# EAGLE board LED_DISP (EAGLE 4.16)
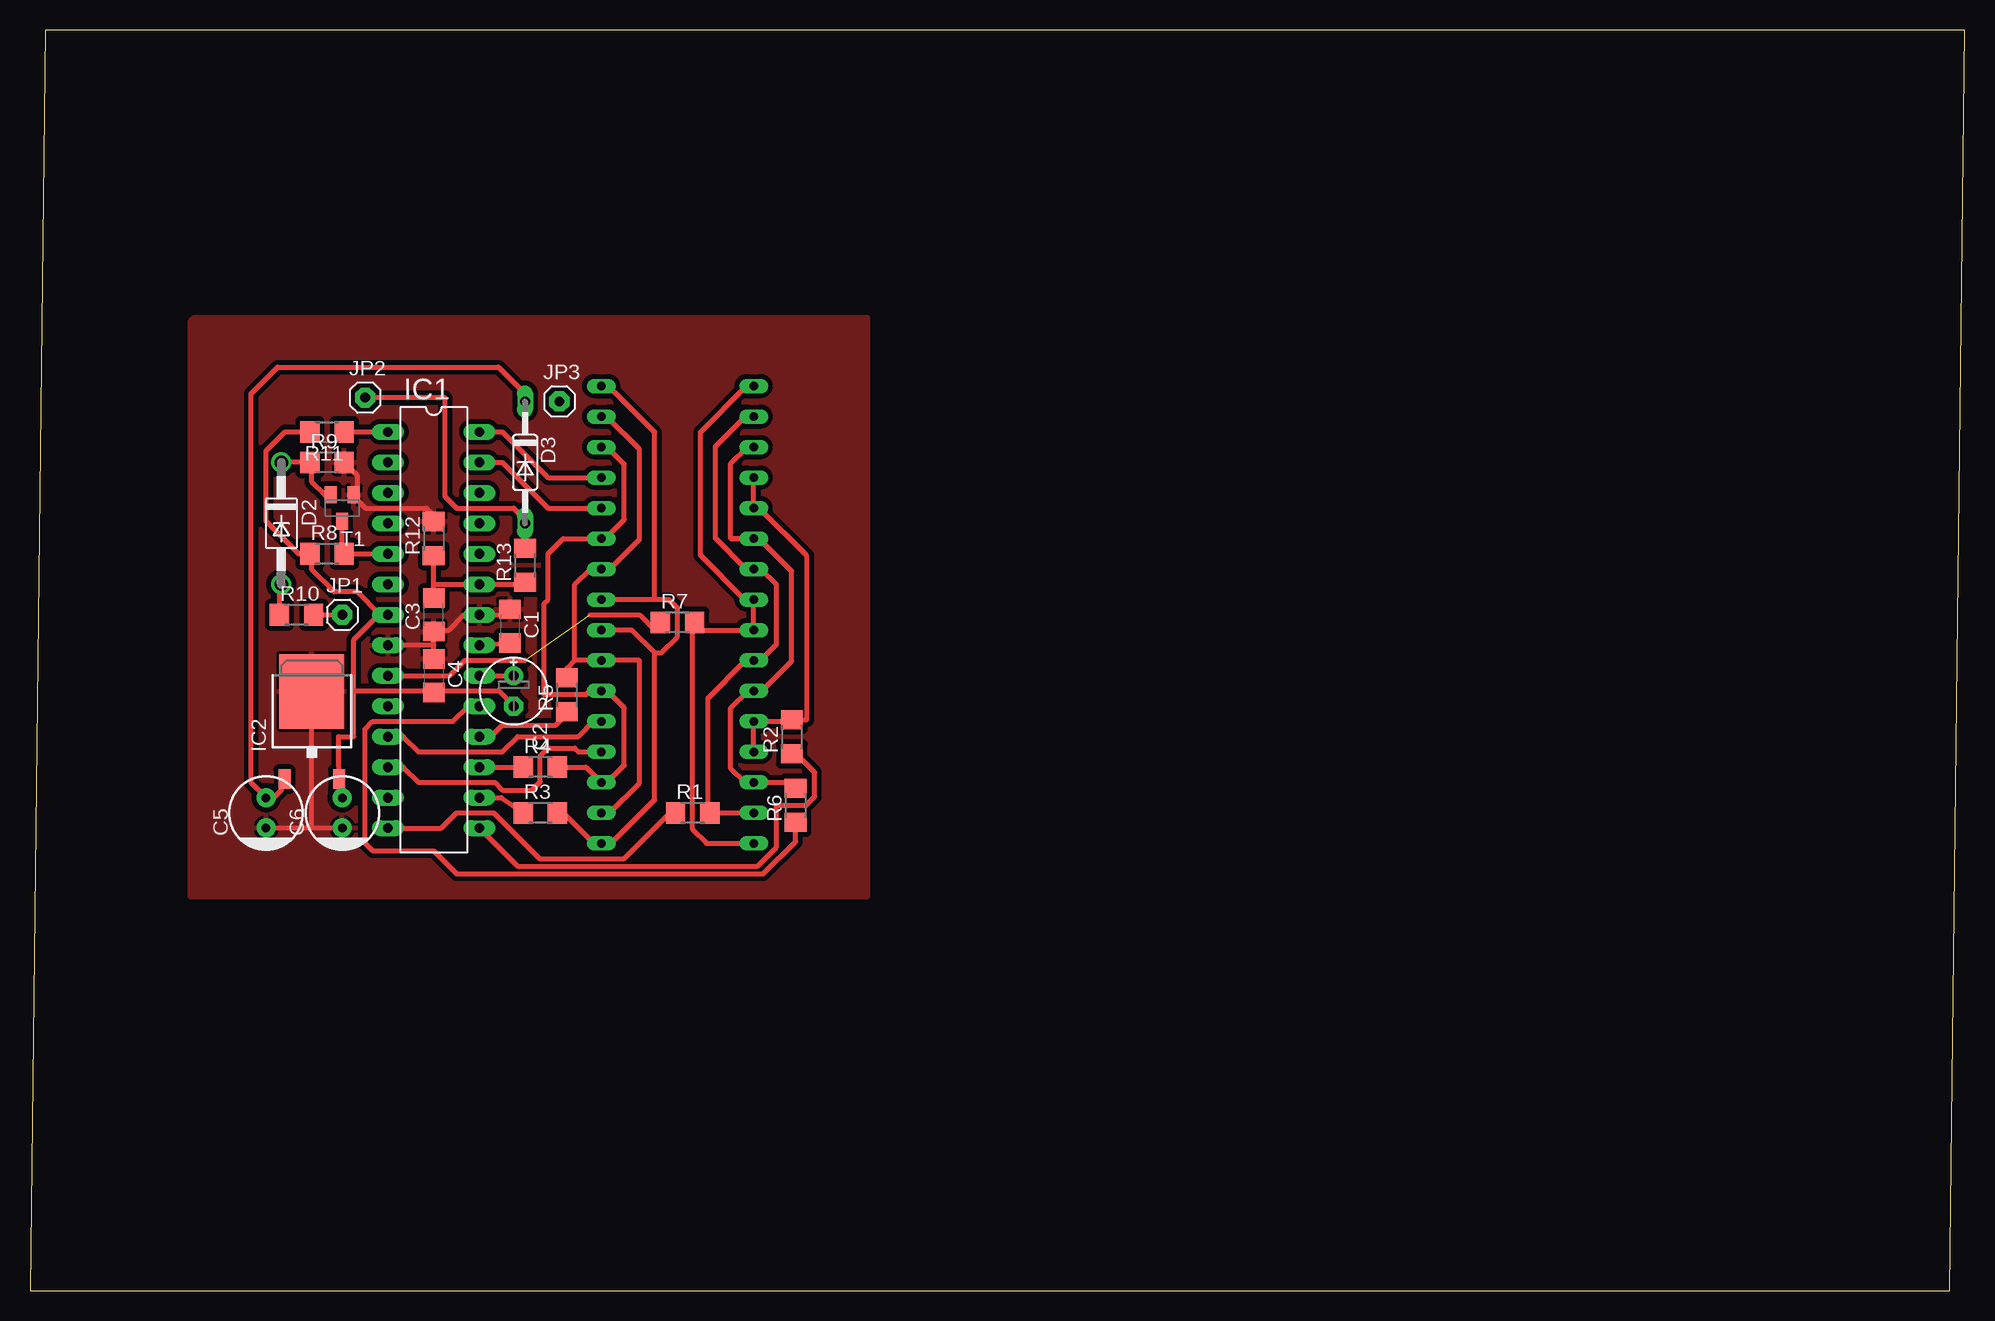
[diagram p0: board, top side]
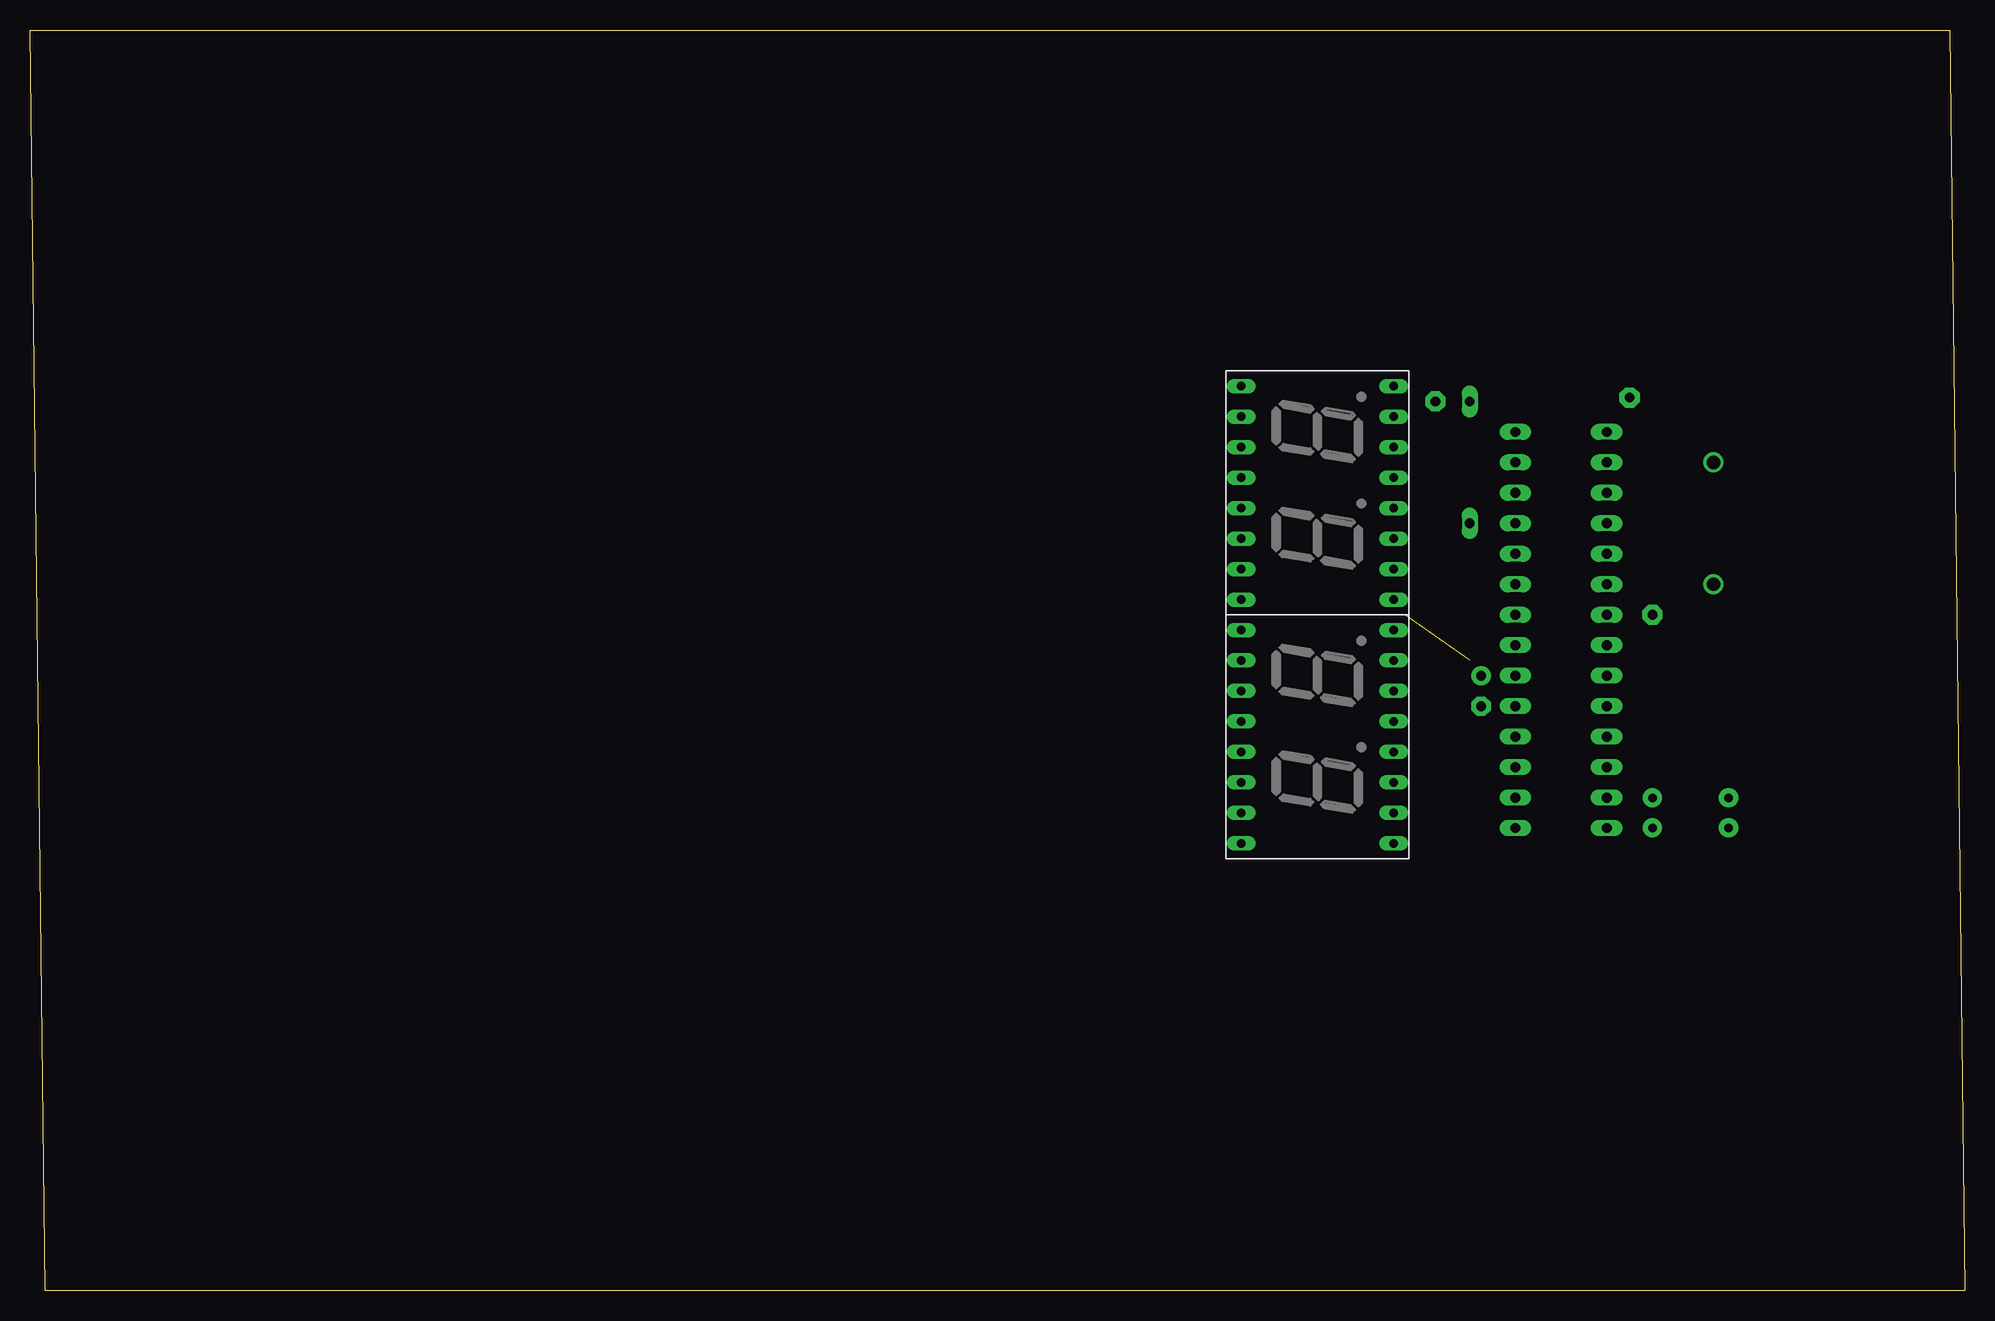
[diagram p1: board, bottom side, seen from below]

Size 161.27 x 105.08 mm. Coordinates in mm from the lower left corner, seen from the top.
Outline: 0,0 160,0 161.27,105.08 1.27,105.08 0,0
Copper layers (1*16): Top 0.035mm / dielectric 1.5mm / Bottom 0.035mm
Design rules "default": minimum track width 10mil, minimum drill 24mil, track to track 8mil, track to pad 8mil, pad to pad 8mil, via to via 8mil, smd to smd 8mil, copper to edge 40mil, drill to drill 8mil, minimum pad ring 10mil, minimum via ring 8mil, stop-mask expansion 4mil, vias tented up to drill 0mil, thermal gap 10mil

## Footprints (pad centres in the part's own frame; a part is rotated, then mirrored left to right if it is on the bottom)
C1206 = smd 1.6 x 1.8: 1 -1.4,0; 2 1.4,0
E2,5-6E = drill 0.813 pad 1.6 round: + -1.27,0 | drill 0.813 pad 1.6 octagon: - 1.27,0
SANYO-OSCON_C6 = drill 0.7 pad 1.6 round: + 1.25,0; - -1.25,0
DO41-10 = drill 1.118 round: A 5.08,0; C -5.08,0
DO35-10 = drill 0.813 long: A 5.08,0; C -5.08,0
DIL28-3 = drill 0.813 long: 1 -16.51,-3.81; 2 -13.97,-3.81; 3 -11.43,-3.81; 4 -8.89,-3.81; 5 -6.35,-3.81; 6 -3.81,-3.81; 7 -1.27,-3.81; 8 1.27,-3.81; 9 3.81,-3.81; 10 6.35,-3.81; 11 8.89,-3.81; 12 11.43,-3.81; 13 13.97,-3.81; 14 16.51,-3.81; 15 16.51,3.81; 16 13.97,3.81; 17 11.43,3.81; 18 8.89,3.81; 19 6.35,3.81; 20 3.81,3.81; 21 1.27,3.81; 22 -1.27,3.81; 23 -3.81,3.81; 24 -6.35,3.81; 25 -8.89,3.81; 26 -11.43,3.81; 27 -13.97,3.81; 28 -16.51,3.81
TO252 = smd 1 x 1.6: 1 -2.28,-4.8; 2 2.28,-4.8 | smd 5.4 x 6.2: 3 0,2.5
1X01 = drill 0.8 pad 1.676 octagon: 1 0,0
R1206 = smd 1.6 x 1.803: 1 -1.422,0; 2 1.422,0
SOT23-EBC = smd 1 x 1.4: B 0.95,-1.1; C 0,1.1; E -0.95,-1.1
DA04 = drill 0.7 long: L$1 -8.89,-3.81; L$2 -6.35,-3.81; L$3 -3.81,-3.81; L$4 -1.27,-3.81; L$5 1.27,-3.81; L$6 3.81,-3.81; L$7 6.35,-3.81; L$8 8.89,-3.81; P$9 8.89,8.89; P$10 6.35,8.89; P$11 3.81,8.89; P$12 1.27,8.89; P$13 -1.27,8.89; P$14 -3.81,8.89; P$15 -6.35,8.89; P$16 -8.89,8.89

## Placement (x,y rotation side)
C1  1uF  [C1206]  40,55.4 270 top
C2  [E2,5-6E]  40.32,50 270 top
C3  1uF  [C1206]  33.65,56.35 90 top
C4  100n  [C1206]  33.65,51.27 270 top
C5  [SANYO-OSCON_C6]  19.68,39.84 90 top
C6  [SANYO-OSCON_C6]  26.03,39.84 90 top
D2  1N4004  [DO41-10]  20.95,63.97 270 top
D3  1N4148  [DO35-10]  41.27,69.05 270 top
IC1  MEGA8-P  [DIL28-3]  33.65,55.08 270 top
IC2  7805DT  [TO252]  23.49,47.46 0 top
JP1  [1X01]  26.03,56.35 0 top
JP2  [1X01]  27.93,74.45 0 top
JP3  [1X01]  44.13,74.13 0 top
R1  120  [R1206]  55.24,39.84 0 top
R2  120  [R1206]  63.49,46.19 90 top
R3  120  [R1206]  42.54,39.84 0 top
R4  120  [R1206]  42.54,43.65 0 top
R5  120  [R1206]  44.76,49.68 90 top
R6  120  [R1206]  63.81,40.47 90 top
R7  120  [R1206]  53.97,55.71 0 top
R8  5k6  [R1206]  24.76,61.43 0 top
R9  10k  [R1206]  24.76,69.05 0 top
R10  4k7  [R1206]  22.22,56.35 0 top
R11  10k  [R1206]  24.76,71.59 180 top
R12  1k2  [R1206]  33.65,62.7 90 top
R13  4k7  [R1206]  41.27,60.48 90 top
T1  [SOT23-EBC]  26.03,65.24 180 top
U$1  DA04-11  [DA04]  51.43,46.19 90 bottom
U$2  DA04-11  [DA04]  51.43,66.51 90 bottom

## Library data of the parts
C1-C6 R1-R13 = rcl
D2 D3 = diode
IC1 = atmel
IC2 = linear
JP1-JP3 = pinhead
T1 = transistor
U$1 U$2 = display-kingbright

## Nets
1: IC1.28 U$2.L$5
2: IC1.27 U$2.L$4
3: IC1.11 U$1.L$5
4: IC1.12 U$1.L$4
+12V: D3.A JP2.1 R13.2
A: R1.2 U$1.P$10 U$1.P$15 U$2.P$10 U$2.P$15
B: R2.2 U$1.P$12 U$1.P$13 U$2.P$12 U$2.P$13
C: R3.2 U$1.L$1 U$1.L$8 U$2.L$1 U$2.L$8
D: R4.2 U$1.L$3 U$1.L$6 U$2.L$3 U$2.L$6
E: R5.2 U$1.L$2 U$1.L$7 U$2.L$2 U$2.L$7
F: R6.2 U$1.P$11 U$1.P$14 U$2.P$11 U$2.P$14
G: R7.2 U$1.P$9 U$1.P$16 U$2.P$9 U$2.P$16
GND: C1.1 C3.1 C4.1 C5.- C6.- IC1.8 IC1.22 IC2.3 R9.2 R12.2 T1.E
N$1: IC1.14 R1.1
N$2: IC1.15 R2.1
N$3: IC1.16 R3.1
N$4: IC1.17 R4.1
N$5: IC1.18 R5.1
N$6: IC1.19 R6.1
N$7: IC1.9 R7.1
N$8: D2.C R9.1 T1.B
N$9: JP1.1 R10.2
N$10: C1.2 IC1.21
N$11: C2.+ IC1.20
N$12: D2.A R10.1
N$13: IC1.1 R11.1
N$14: C3.2 IC1.23 R12.1 R13.1
N$15: C5.+ D3.C IC2.1
N$16: JP3.1
TAHO: IC1.5 R8.2 T1.C
VCC: C2.- C4.2 C6.+ IC1.7 IC2.2 R8.1 R11.2

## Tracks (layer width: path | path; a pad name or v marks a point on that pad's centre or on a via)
1
  Top 0.406: U$2.L$5 43.17,67.78 39.37,71.59 IC1.28
2
  Top 0.406: IC1.27 39.37,69.05 43.17,65.24 U$2.L$4
3
  Top 0.406: U$1.L$5 46.98,47.46 45.71,46.19 40.63,46.19 39.37,44.92 32.38,44.92 31.11,46.19 IC1.11
4
  Top 0.406: U$1.L$4 45.71,44.92 45.4,45.24 43.17,45.24 42.54,44.6 42.54,42.45 41.83,41.74 39.37,41.74 38.73,42.38 32.38,42.38 31.11,43.65 IC1.12
+12V
  Top 0.406: D3.A R13.2 41.27,64.29 40.32,65.24 35.55,65.24 34.6,66.19 34.6,74.45 JP2.1
A
  Top 0.406: U$2.P$10 59.62,72.86 57.14,70.38 57.14,62.72 59.7,60.16 U$2.P$15 60.92,60.16 62.23,58.85 62.23,53.89 60.88,52.54 U$1.P$10 59.65,52.54 56.51,49.4 56.51,39.84 | 56.51,39.84 U$1.P$15 | R1.2 56.51,39.84
B
  Top 0.406: U$2.P$12 U$2.P$13 60.79,65.24 64.77,61.26 64.77,47.61 R2.2 63.49,47.46 U$1.P$12 U$1.P$13
C
  Top 0.406: 52.06,53.17 52.06,40.92 48.45,37.3 U$1.L$1 46.98,37.3 44.45,39.84 R3.2 | 52.06,53.17 50.16,55.08 U$1.L$8 | 52.06,57.62 52.06,71.58 48.24,75.4 U$2.L$8 | 52.06,57.62 U$2.L$1 | 52.06,57.62 53.26,57.62 53.97,56.91 53.97,54.52 52.62,53.17 52.06,53.17
D
  Top 0.406: U$2.L$6 48.1,70.32 49.52,68.9 49.52,64.29 47.94,62.7 U$2.L$3 44.45,62.7 43.17,61.43 43.17,57.62 42.86,57.3 42.86,49.68 46.35,49.68 46.67,50 U$1.L$6 48.1,50 49.52,48.58 49.52,43.8 48.1,42.38 U$1.L$3 46.35,43.65 R4.2
E
  Top 0.406: U$2.L$7 48.06,72.86 50.8,70.13 50.8,62.64 48.31,60.16 U$2.L$2 46.67,60.16 45.4,58.89 45.4,52.54 | U$1.L$2 48.31,39.84 50.8,42.32 50.8,52.54 U$1.L$7 47.3,52.54 | 47.3,52.54 46.98,52.54 | R5.2 44.76,51.9 45.4,52.54 | 47.3,52.54 45.4,52.54
F
  Top 0.406: 58.41,62.7 58.41,68.97 59.76,70.32 U$2.P$11 | 58.41,62.7 U$2.P$14 | 58.41,62.7 60.78,62.7 63.49,59.99 63.49,52.48 61.02,50 U$1.P$11 59.84,50 58.41,48.58 58.41,43.52 59.56,42.38 U$1.P$14 63.49,42.38 R6.2
G
  Top 0.406: U$2.P$9 59.7,75.4 55.88,71.58 55.88,61.32 59.58,57.62 U$2.P$16 U$1.P$9 55.24,55.08 | 55.88,55.71 R7.2 55.24,55.71 55.24,55.08 | 55.24,55.08 55.24,38.45 56.38,37.3 U$1.P$16
GND
  Top 0.406: C4.1 33.65,53.81 | 33.65,53.81 C3.1 33.65,55.08 34.92,55.08 36.19,56.35 IC1.22 40,56.35 C1.1 | 33.65,53.81 IC1.8 | T1.E 27.3,66.34 | 26.03,69.05 R9.2 27.3,67.93 27.3,66.34 | 27.3,66.34 27.3,65.88 27.93,65.24 33.02,65.24 33.65,64.61 R12.2 | C6.- 26.03,38.57 26.01,38.59 23.49,38.59 | C5.- 23.49,38.59 | 23.49,38.59 23.49,38.57 | 23.49,38.59 IC2.3
  pour Top (isolate 0.406): 13.33,80.8 13.33,32.85 69.84,32.85 69.84,81.11 13.65,81.11
  pour Top (isolate 0.406): 13.33,80.8 13.33,32.85 69.84,32.85 69.84,81.11 13.65,81.11
N$1
  Top 0.406: R1.1 53.34,39.84 49.52,36.03 42.46,36.03 39.37,39.13 38.66,39.84 35.55,39.84 34.28,38.57 IC1.14
N$2
  Top 0.406: R2.1 63.49,44.92 63.69,44.92 65.4,43.21 65.4,41.18 64.69,40.47 62.23,40.47 62.23,36.98 60.64,35.39 40.63,35.39 IC1.15
N$3
  Top 0.406: IC1.16 39.28,41.11 R3.1
N$4
  Top 0.406: IC1.17 R4.1
N$5
  Top 0.406: IC1.18 38.41,46.19 39.37,47.14 43.81,47.14 44.76,48.09 R5.1
N$6
  Top 0.406: R6.1 63.81,37.45 61.12,34.76 35.55,34.76 33.65,36.66 28.57,36.66 27.93,37.3 27.93,46.82 28.57,47.46 35.24,47.46 36.51,48.73 IC1.19
N$7  (1 unrouted)
  Top 0.406: IC1.9 34.99,51.27 36.27,52.54 41.27,52.54 | 52.06,55.08 R7.1 | 52.06,55.08 52.06,56.35 | 52.06,55.08 50.8,56.35 46.67,56.35
N$8
  Top 0.406: T1.B 24.56,66.34 23.49,67.41 23.49,69.05 R9.1 D2.C
N$9
  Top 0.406: R10.2 JP1.1
N$10
  Top 0.406: IC1.21 C1.2
N$11
  Top 0.406: IC1.20 C2.+
N$12
  Top 0.406: R10.1 20.8,58.74 D2.A
N$13
  Top 0.406: 26.03,71.59 R11.1 IC1.1
N$14
  Top 0.406: 33.65,57.62 C3.2 33.65,58.89 | 33.65,58.89 IC1.23 41.27,58.89 R13.1 | 33.65,61.43 R12.1 33.65,58.89
N$15
  Top 0.406: IC2.1 21.21,42.64 20.95,42.38 20.95,41.74 20.29,41.09 C5.+ 19.68,41.11 18.42,42.37 18.42,74.78 20.63,76.99 39.05,76.99 41.27,74.77 D3.C
TAHO
  Top 0.406: IC1.5 R8.2 26.03,61.43 T1.C
VCC
  Top 0.406: C2.- 39.05,50 33.65,50 | 23.49,71.59 R11.2 21.27,71.59 19.68,70 19.68,64.14 22.39,61.43 R8.1 23.49,61.43 23.49,60.11 25.34,58.25 27.3,58.25 29.2,56.35 IC1.7 29.08,56.35 26.98,54.25 26.98,50 | C6.+ 26.03,41.11 25.77,41.37 IC2.2 25.77,42.75 25.71,44.6 25.71,46.19 26.98,46.19 26.98,50 | 33.65,50 C4.2 | 26.98,50 33.65,50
